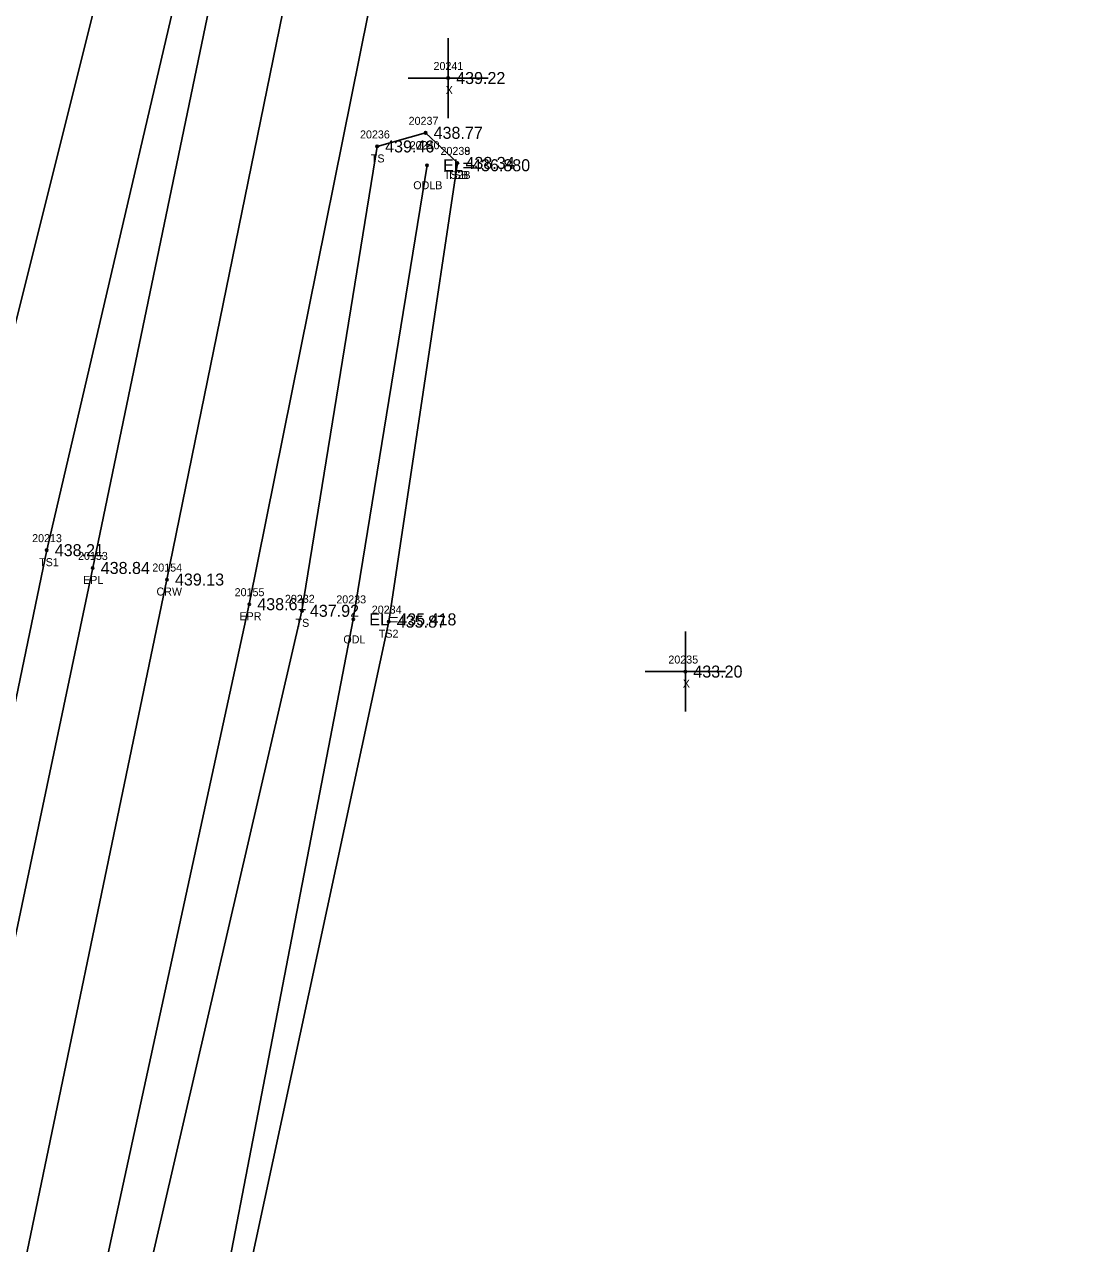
# Model space of a CAD drawing. Extents: x 1755707 to 1756750, y 975854 to 977363.
# Drawn here: x 1756236.1 to 1756368.5, y 976760.4 to 976912.7 of the extents above; entities that cross this region are included whole.
import ezdxf

# ---------------------------------------------------------------- set-up
doc = ezdxf.new("R2010")
doc.units = 0
for name, color, linetype in [('RD_DTM_BkLn1', 7, 'Continuous'), ('RD_DTM_BkLn2', 7, 'Continuous'), ('RD_DTM_BkLn_txCode', 7, 'Continuous'), ('RD_EX_H2O', 7, 'Continuous'), ('RD_EX_H2O_txCode', 7, 'Continuous'), ('RD_EX_Misc', 7, 'Continuous'), ('RD_EX_Misc_txCode', 7, 'Continuous'), ('RD_EX_Road', 7, 'Continuous'), ('RD_EX_Road_txCode', 7, 'Continuous'), ('RD_EX_TX_H2O_ELEV', 7, 'Continuous'), ('RD_EX_TX_Misc_ELEV', 7, 'Continuous'), ('RD_EX_TX_Road_ELEV', 7, 'Continuous'), ('RD_HC_Survey_ELEV', 7, 'Continuous'), ('RD_HC_Survey_txCode', 7, 'Continuous'), ('RD_SMD_Locator', 7, 'Continuous')]:
    doc.layers.add(name, color=color, linetype=linetype)

msp = doc.modelspace()

# ---------------------------------------------------------------- linework, layer by layer
at = {"layer": 'RD_DTM_BkLn1'}
msp.add_lwpolyline([(1756212.24, 976646.92), (1756233.31, 976744.58), (1756253.87, 976843.36), (1756274.18, 976942.87), (1756294.7, 977044.28), (1756314.7, 977141.54), (1756335.65, 977241.96), (1756357.9, 977342.03)], dxfattribs=at)
at = {"layer": 'RD_DTM_BkLn2'}
for points in [[(1756101.82, 976704.9), (1756150.92, 976716.16), (1756211.72, 976728.04), (1756216.23, 976737.89), (1756238.86, 976847.03), (1756261.79, 976945.44), (1756283.19, 977044.99), (1756303.06, 977145.95), (1756325.46, 977245.55), (1756346.55, 977344.09)], [(1756101.82, 976704.9), (1756144.73, 976723.58), (1756149.68, 976727.6), (1756152.89, 976726.7), (1756204.3, 976738.63), (1756228.54, 976849.91), (1756252.92, 976947.37), (1756266.62, 977008.29)], [(1756228.43, 976635.42), (1756229.64, 976650.51), (1756228.61, 976661.27), (1756248.15, 976741.84), (1756270.72, 976839.45), (1756280.12, 976897.48), (1756286.17, 976899.18), (1756290.15, 976895.42)], [(1756247.6, 976631.15), (1756240.42, 976640.71), (1756260.5, 976740.01), (1756281.57, 976838.1), (1756290.15, 976895.42)]]:
    msp.add_lwpolyline(points, dxfattribs=at)
at = {"layer": 'RD_EX_H2O'}
msp.add_lwpolyline([(1756242.15, 976615.93), (1756239.38, 976632.15), (1756237.67, 976640.34), (1756258.24, 976740.24), (1756277.14, 976838.38), (1756286.35, 976895.13)], dxfattribs=at)
at = {"layer": 'RD_EX_Misc'}
for p, q in [((1756288.99, 976901.03), (1756288.99, 976911.03)), ((1756283.99, 976906.03), (1756293.99, 976906.03)), ((1756318.61, 976826.86), (1756318.61, 976836.86)), ((1756313.61, 976831.86), (1756323.61, 976831.86))]:
    msp.add_line(p, q, dxfattribs=at)
at = {"layer": 'RD_EX_Road'}
for points in [[(1756212.24, 976646.92), (1756202.87, 976648.96), (1756215.01, 976705.04), (1756220.09, 976730.75), (1756223.91, 976746.46), (1756244.6, 976844.81), (1756265.35, 976944.71), (1756286.1, 977045.83), (1756306.04, 977143.32), (1756326.71, 977243.79), (1756348.97, 977343.58)], [(1756212.24, 976646.92), (1756220.86, 976645.39), (1756242.73, 976741.74), (1756264.15, 976840.28), (1756284.31, 976940.54), (1756305.17, 977042.39), (1756325.03, 977140.07), (1756346.16, 977239.41), (1756368.47, 977341.2)]]:
    msp.add_lwpolyline(points, dxfattribs=at)
at = {"layer": 'RD_SMD_Locator'}
for centre in [(1756288.99, 976906.03), (1756286.17, 976899.18), (1756280.12, 976897.48), (1756286.35, 976895.13), (1756290.15, 976895.42), (1756290.15, 976895.42), (1756238.86, 976847.03), (1756244.6, 976844.81), (1756253.87, 976843.36), (1756264.15, 976840.28), (1756270.72, 976839.45), (1756277.14, 976838.38), (1756281.57, 976838.1), (1756318.61, 976831.86)]:
    msp.add_circle(centre, 0.15, dxfattribs=at)

# ---------------------------------------------------------------- texts
at = {"layer": 'RD_DTM_BkLn_txCode'}
for s, p in [('20237', (1756284.05, 976900.18)), ('20236', (1756277.98, 976898.48)), ('TS', (1756285.37, 976897.18)), ('20238', (1756288.03, 976896.42)), ('20239', (1756288.03, 976896.42)), ('TS', (1756279.33, 976895.48)), ('TS2B', (1756288.44, 976893.42)), ('TSB', (1756288.88, 976893.42)), ('20213', (1756237.03, 976848.03)), ('TS1', (1756237.9, 976845.03)), ('20232', (1756268.6, 976840.45)), ('20234', (1756279.45, 976839.1)), ('TS', (1756269.93, 976837.45)), ('TS2', (1756280.33, 976836.1))]:
    msp.add_text(s, height=1, dxfattribs=at).set_placement(p)
at = {"layer": 'RD_EX_H2O_txCode'}
for s, p in [('20240', (1756284.19, 976897.13)), ('ODLB', (1756284.63, 976892.13)), ('20233', (1756275.02, 976840.38)), ('ODL', (1756275.9, 976835.38))]:
    msp.add_text(s, height=1, dxfattribs=at).set_placement(p)
at = {"layer": 'RD_EX_Misc_txCode'}
for s, p in [('20241', (1756287.16, 976907.03)), ('X', (1756288.68, 976904.03)), ('20235', (1756316.49, 976832.86)), ('X', (1756318.29, 976829.86))]:
    msp.add_text(s, height=1, dxfattribs=at).set_placement(p)
at = {"layer": 'RD_EX_Road_txCode'}
for s, p in [('20153', (1756242.76, 976845.81)), ('EPL', (1756243.39, 976842.81)), ('20155', (1756262.32, 976841.28)), ('EPR', (1756262.92, 976838.28))]:
    msp.add_text(s, height=1, dxfattribs=at).set_placement(p)
at = {"layer": 'RD_EX_TX_H2O_ELEV'}
for s, p in [('EL=436.880', (1756288.35, 976894.38)), ('EL=435.418', (1756279.14, 976837.63))]:
    msp.add_text(s, height=1.5, dxfattribs=at).set_placement(p)
at = {"layer": 'RD_EX_TX_Misc_ELEV'}
for s, p in [('439.22', (1756289.99, 976905.28)), ('438.77', (1756287.17, 976898.43)), ('439.46', (1756281.12, 976896.73)), ('438.34', (1756291.15, 976894.67)), ('438.34', (1756291.15, 976894.67)), ('438.21', (1756239.86, 976846.28)), ('437.92', (1756271.72, 976838.7)), ('435.87', (1756282.57, 976837.35)), ('433.20', (1756319.61, 976831.11))]:
    msp.add_text(s, height=1.5, dxfattribs=at).set_placement(p)
at = {"layer": 'RD_EX_TX_Road_ELEV'}
for s, p in [('438.84', (1756245.6, 976844.06)), ('438.61', (1756265.15, 976839.53))]:
    msp.add_text(s, height=1.5, dxfattribs=at).set_placement(p)
at = {"layer": 'RD_HC_Survey_ELEV'}
msp.add_text('439.13', height=1.5, dxfattribs=at).set_placement((1756254.87, 976842.61))
at = {"layer": 'RD_HC_Survey_txCode'}
for s, p in [('20154', (1756252.04, 976844.36)), ('CRW', (1756252.56, 976841.36))]:
    msp.add_text(s, height=1, dxfattribs=at).set_placement(p)

doc.saveas('drawing.dxf')
